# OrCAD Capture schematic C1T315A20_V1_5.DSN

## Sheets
1 000_LOG: title: TELINK; rev: V1.4; note: C1T315A20
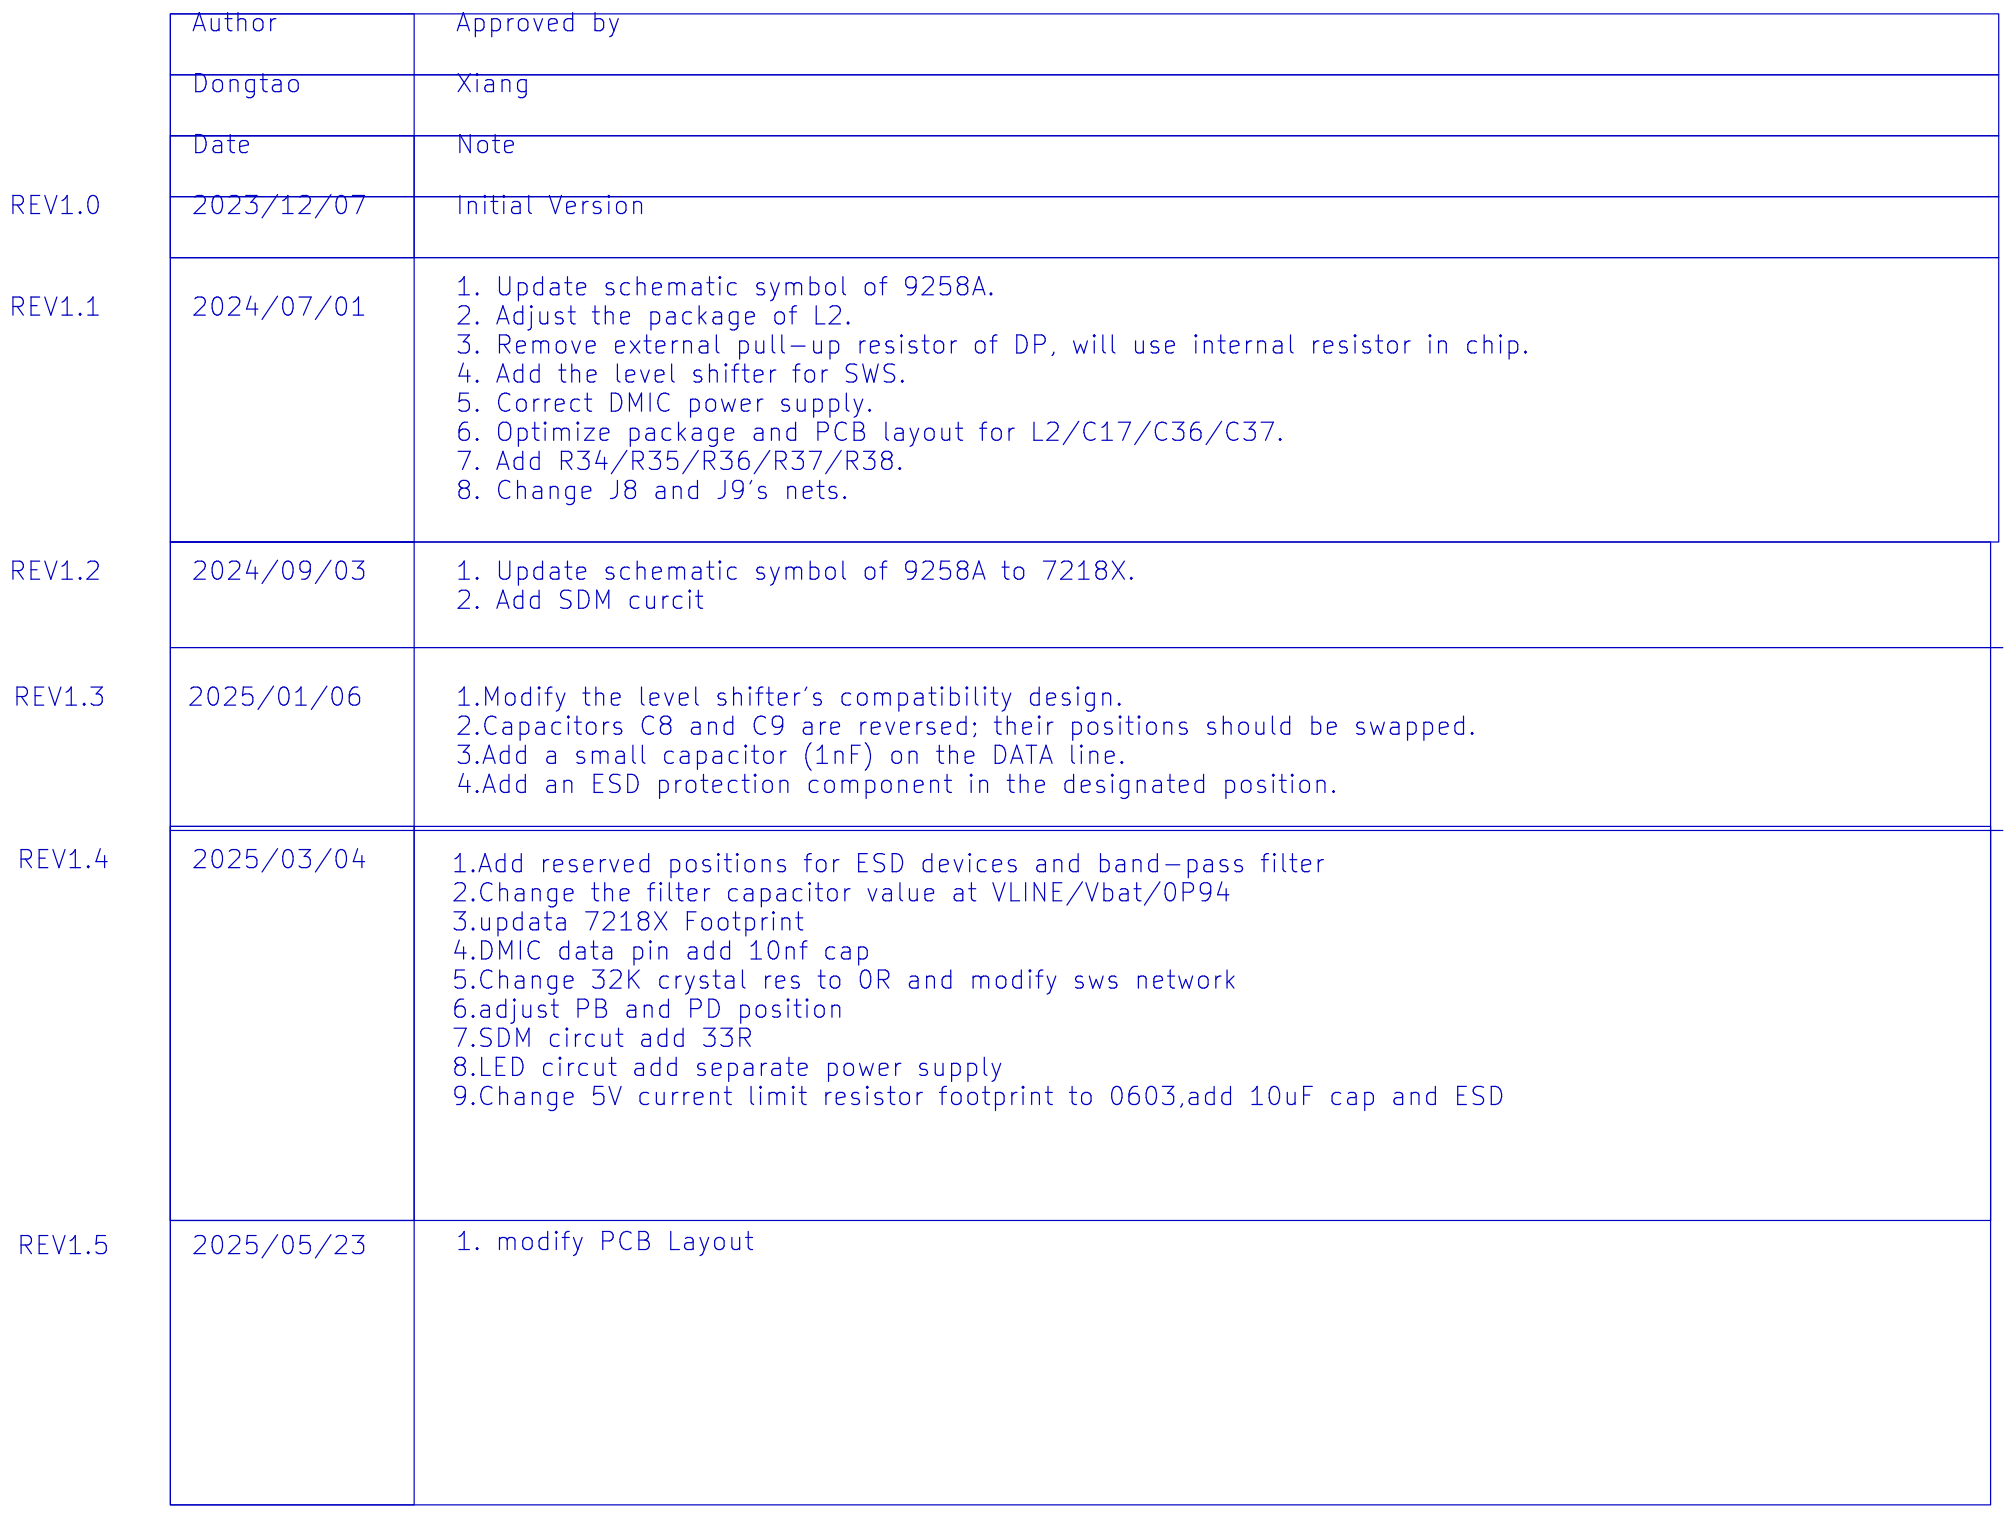
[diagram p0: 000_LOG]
2 001_STR: rev: V1.5
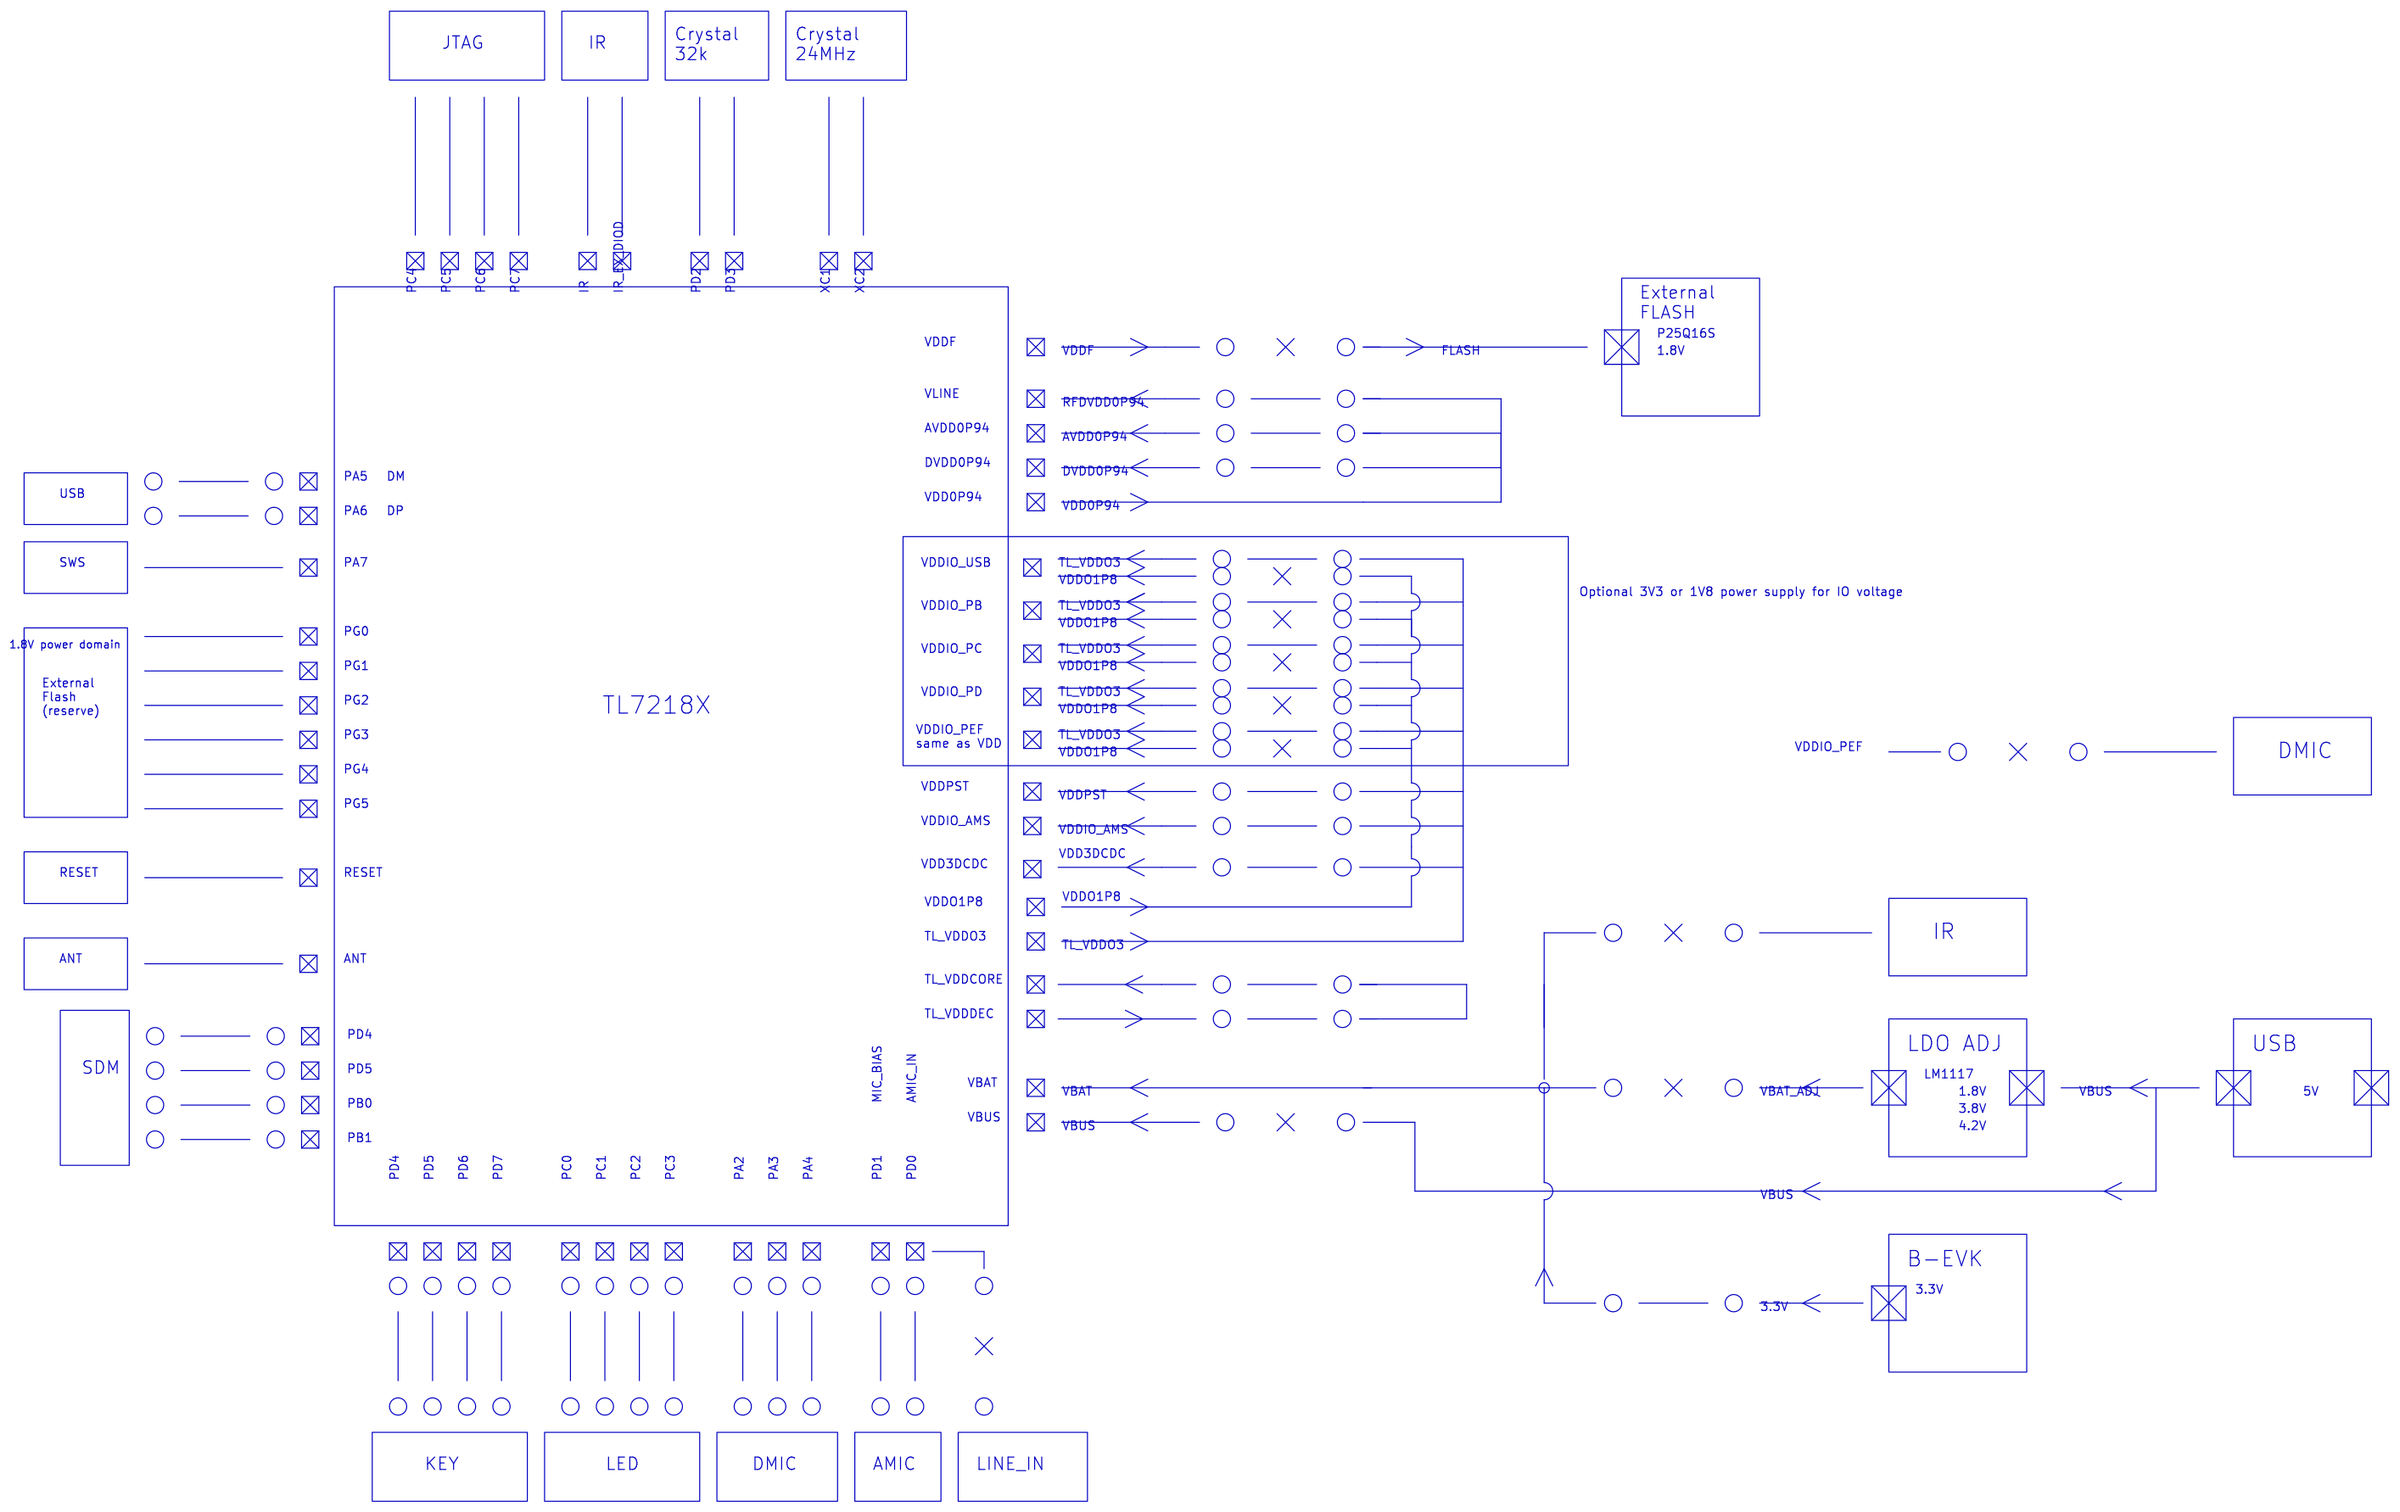
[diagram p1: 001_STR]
3 002_MAIN: size A3; rev: V1.5
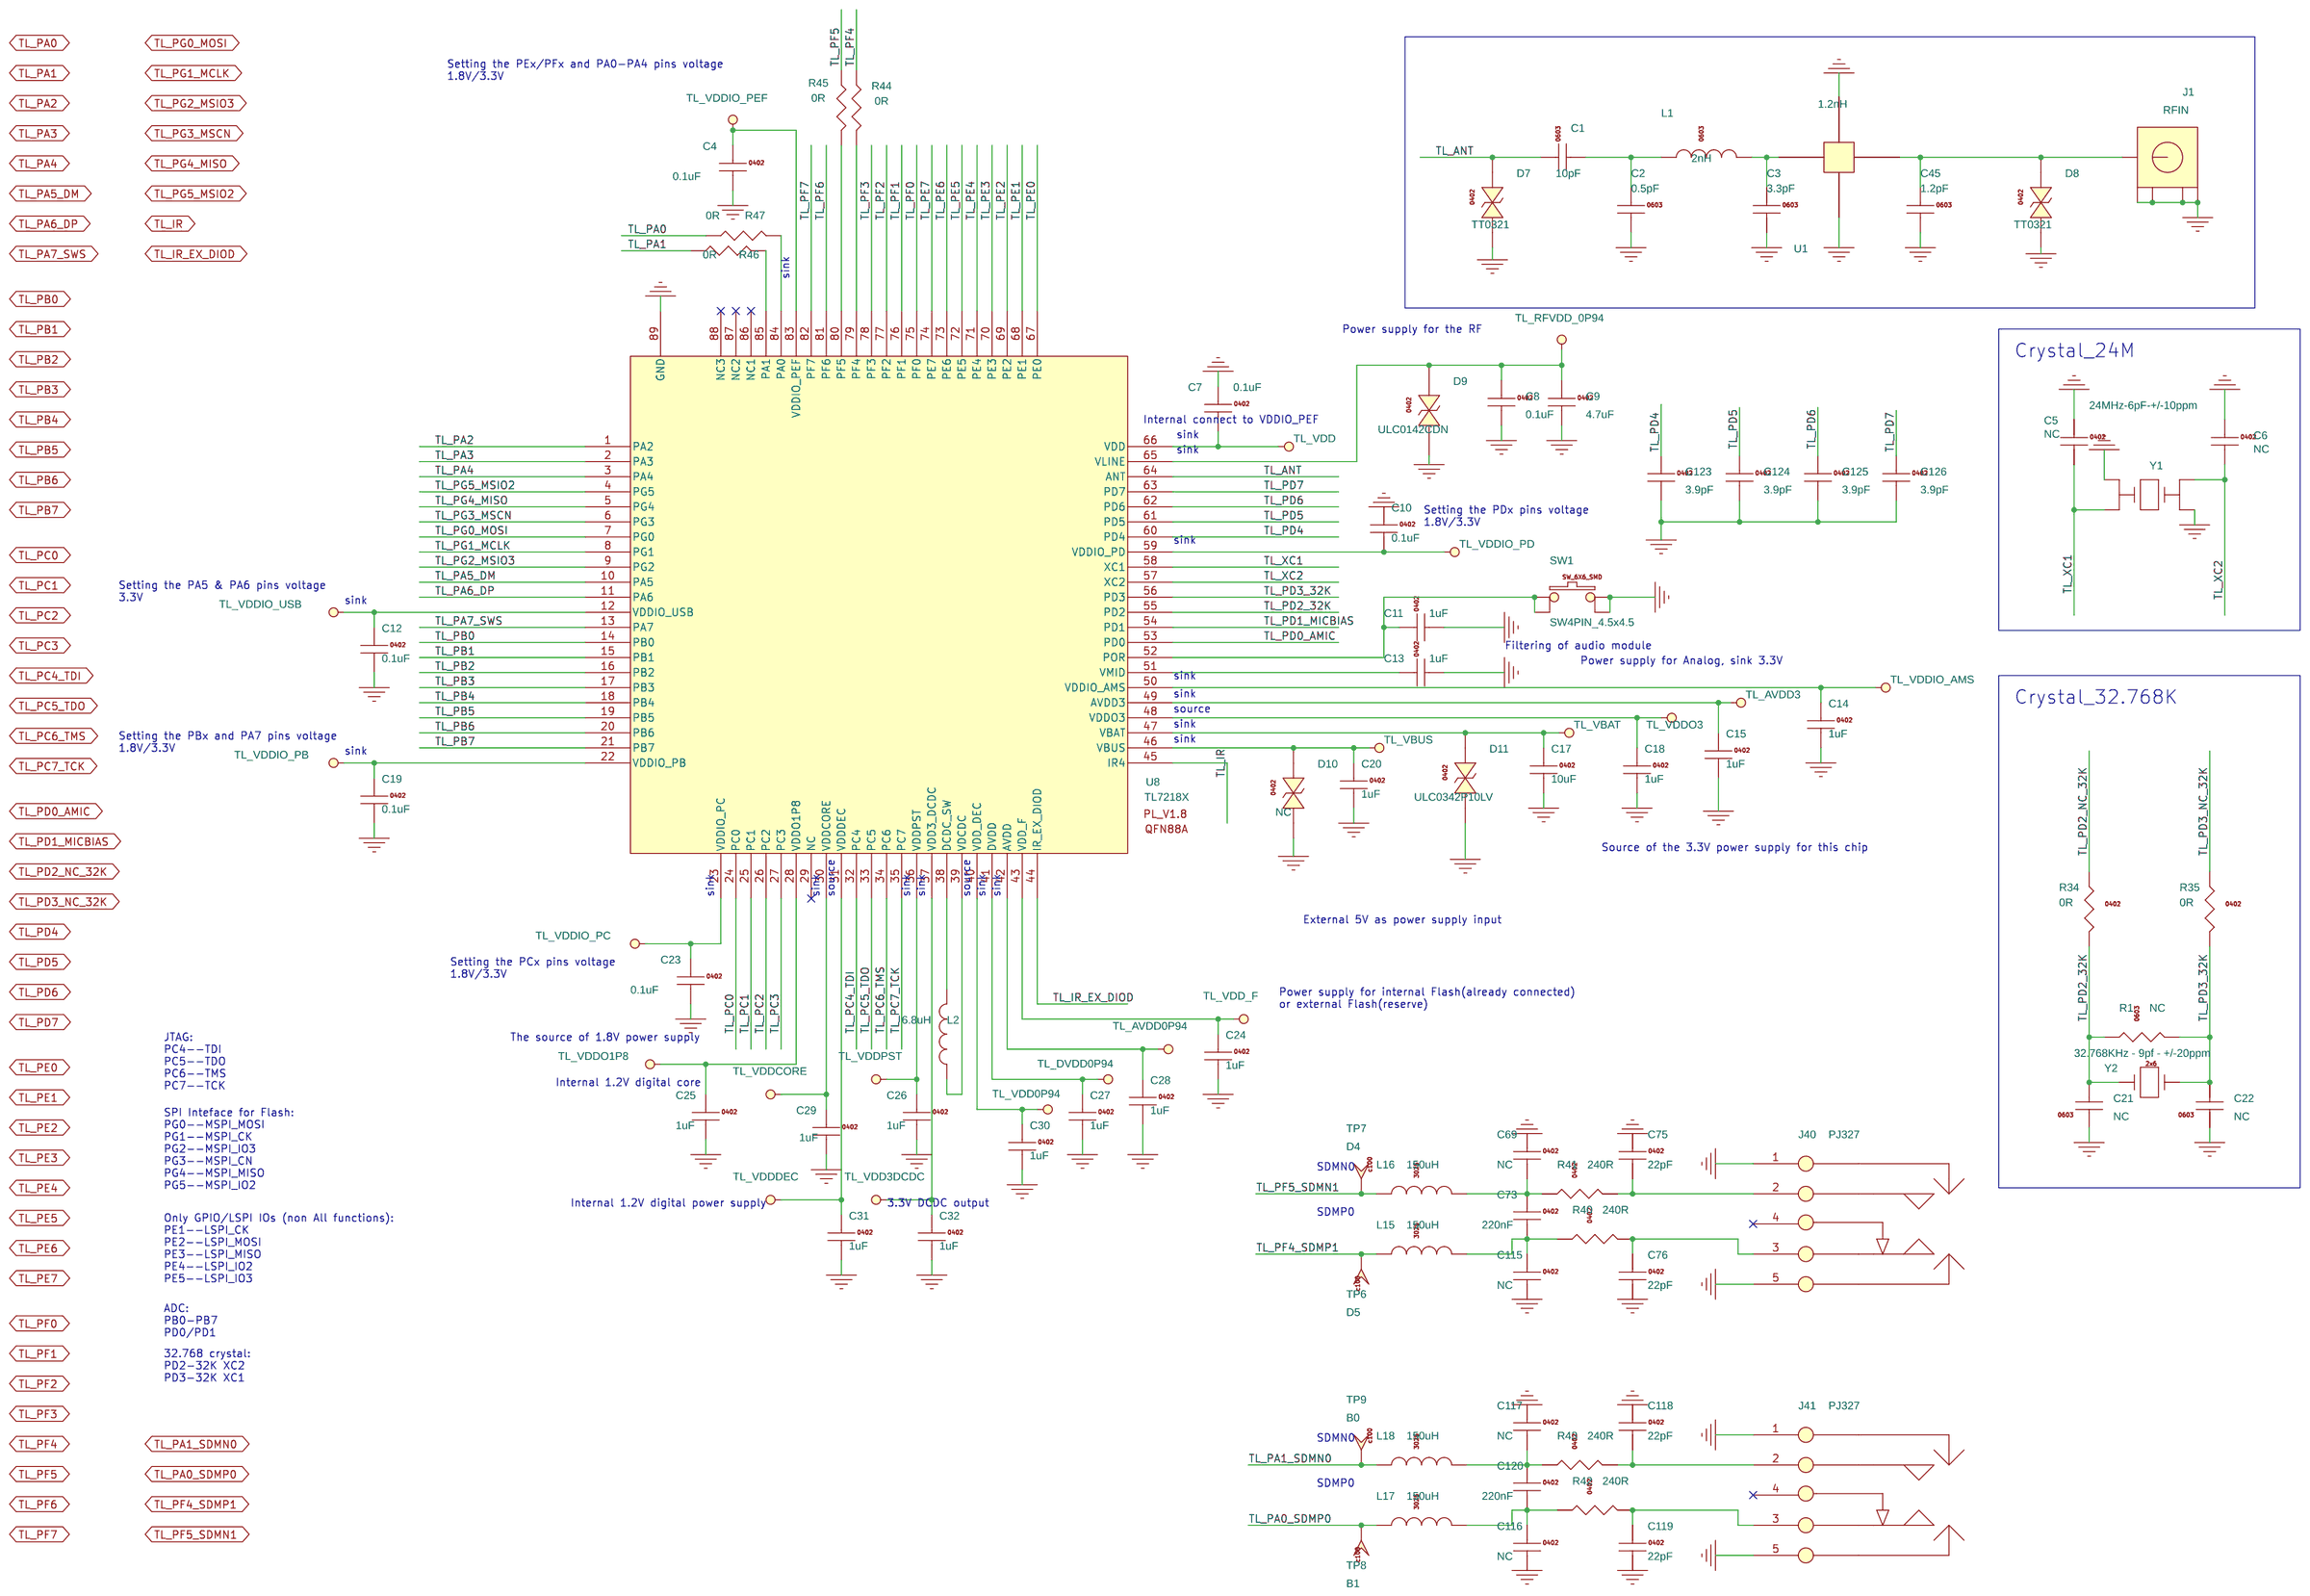
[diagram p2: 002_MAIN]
4 003_INTERFACE: size A3; rev: V1.5
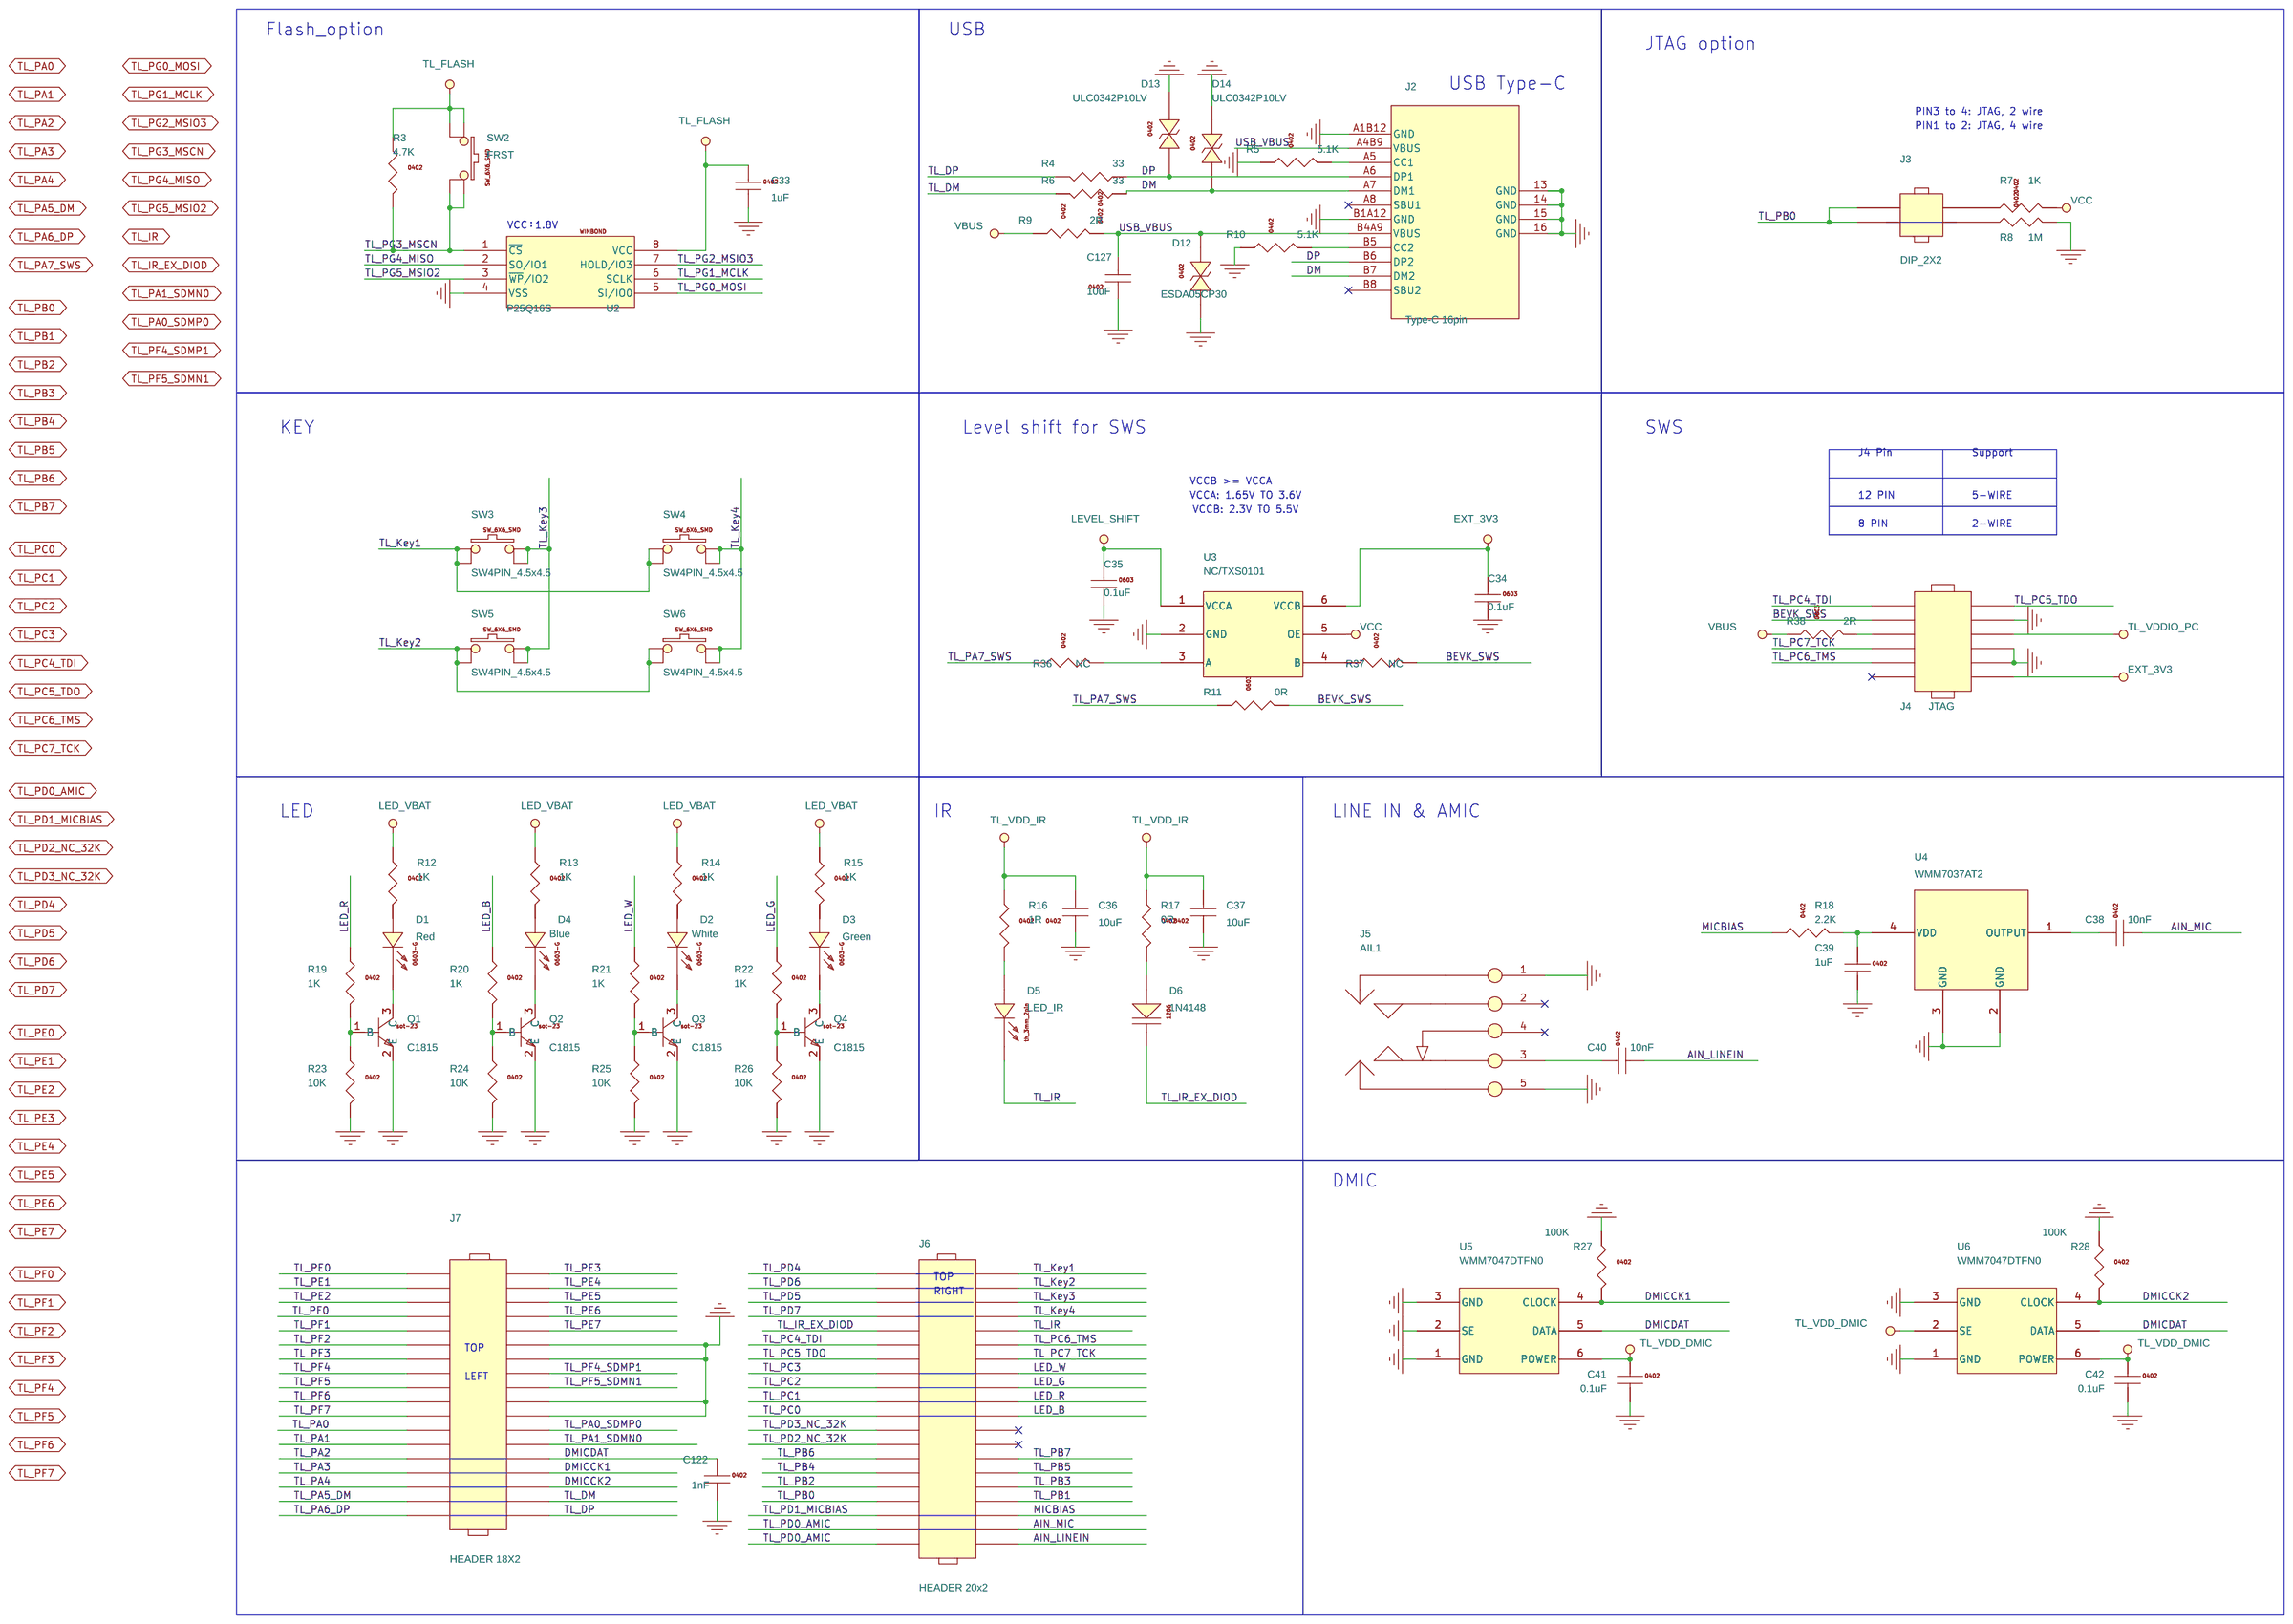
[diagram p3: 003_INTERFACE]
5 004_POWER: size A4; rev: V1.5
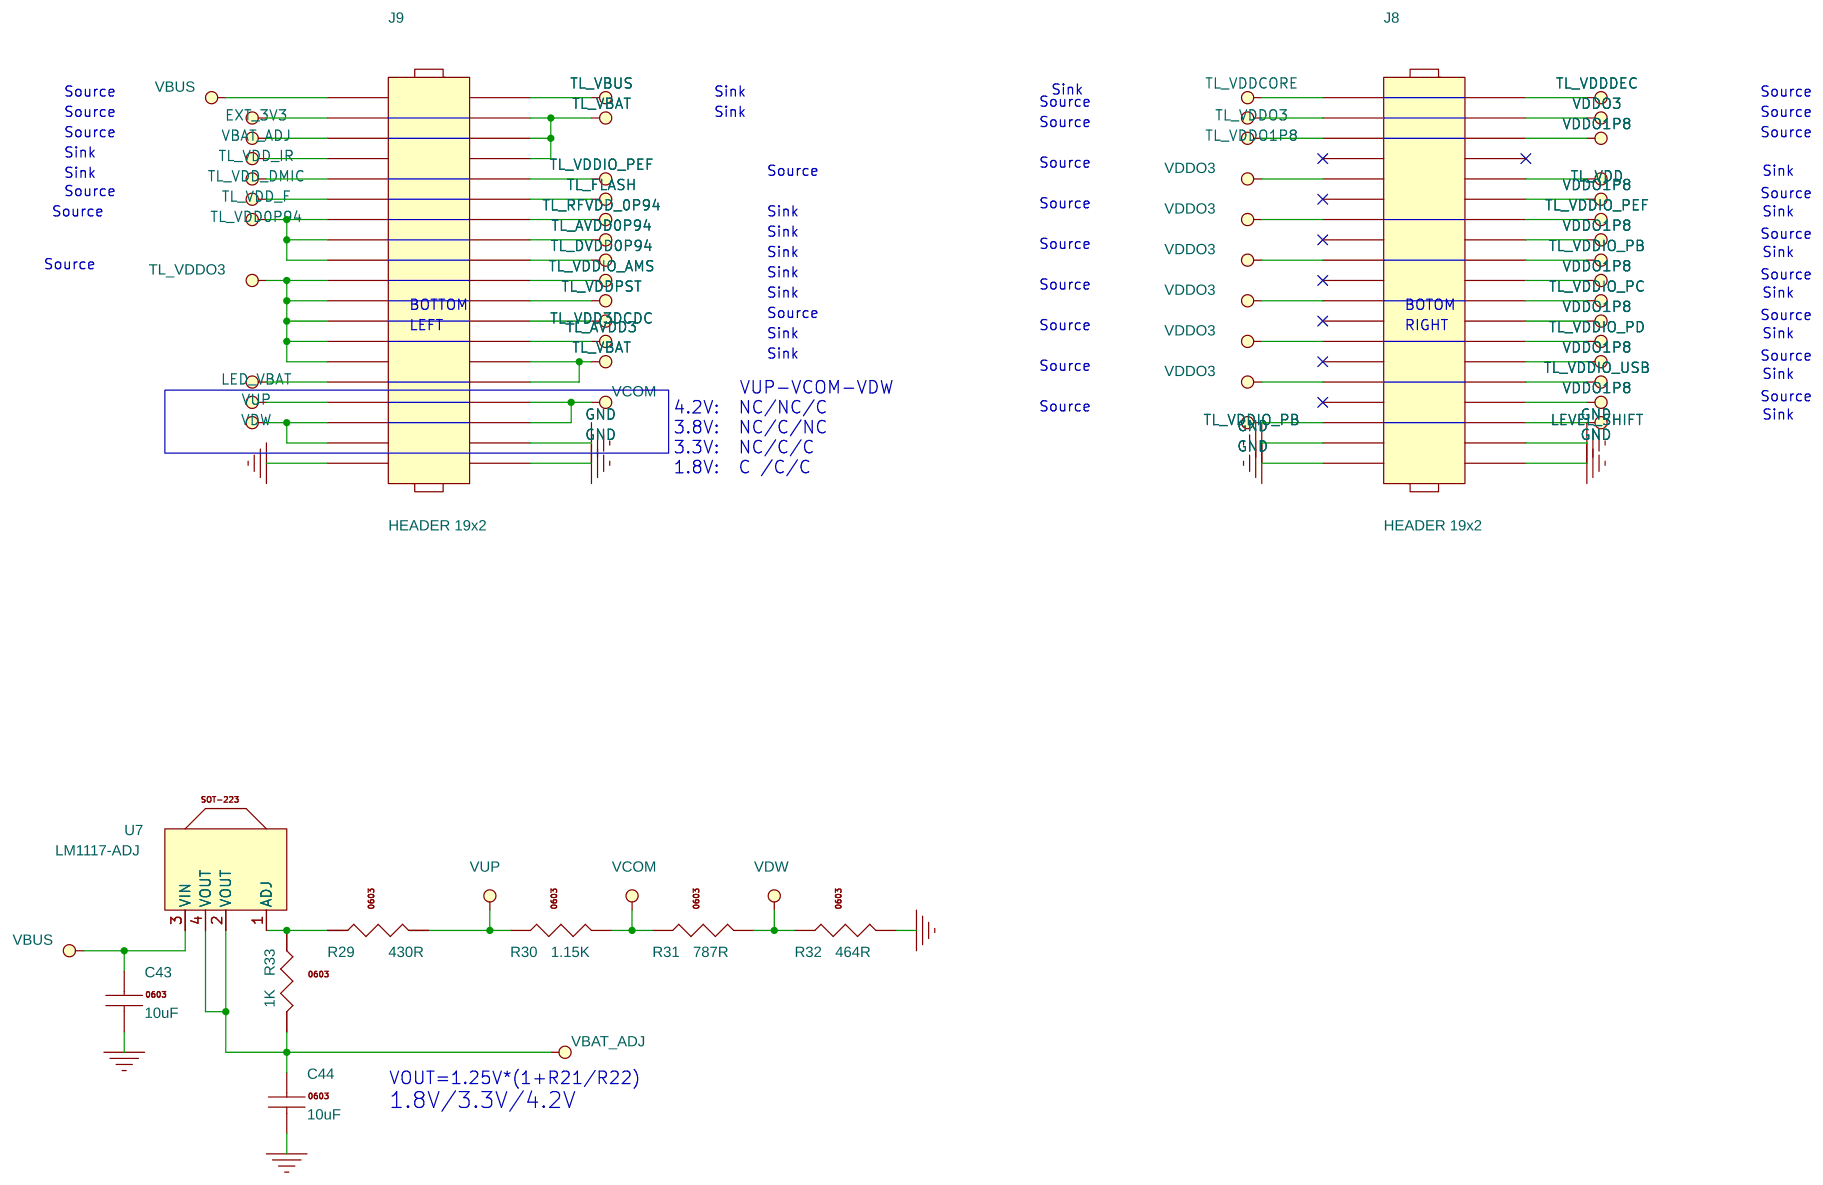
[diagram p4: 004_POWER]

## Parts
sheet 002_MAIN
C1  10pF  [0402]
C2  0.5pF  [0402]
C3  3.3pF  [0402]
C4  0.1uF  [0402]
C5  NC  [0402]
C6  NC  [0402]
C7  0.1uF  [0402]
C8  0.1uF  [0402]
C9  4.7uF  [0402]
C10  0.1uF  [0402]
C11  1uF  [0402]
C12  0.1uF  [0402]
C13  1uF  [0402]
C14  1uF  [0402]
C15  1uF  [0402]
C17  10uF  [0603C]
C18  1uF  [0402]
C19  0.1uF  [0402]
C20  1uF  [0402]
C21  NC  [0402]
C22  NC  [0402]
C23  0.1uF  [0402]
C24  1uF  [0402]
C25  1uF  [0402]
C26  1uF  [0402]
C27  1uF  [0402]
C28  1uF  [0402]
C29  1uF  [0402]
C30  1uF  [0402]
C31  1uF  [0402]
C32  1uF  [0402]
C45  1.2pF  [0402]
C69  NC  [0402]
C73  220nF  [0402]
C75  22pF  [0402]
C76  22pF  [0402]
C115  NC  [0402]
C116  NC  [0402]
C117  NC  [0402]
C118  22pF  [0402]
C119  22pF  [0402]
C120  220nF  [0402]
C123  3.9pF  [0402]
C124  3.9pF  [0402]
C125  3.9pF  [0402]
C126  3.9pF  [0402]
D7  TT0321  [0402]
D8  TT0321  [0402]
D9  ULC0142CDN  [0402]
D10  NC  [0402]
D11  ULC0342P10LV  [0402]
J1  RFIN  [SMA-H]
J40  PJ327  [PJ-327]
J41  PJ327  [PJ-327]
L1  2nH  [0402]
L2  6.8uH  [1008L]
L15  150uH  [INDM3025X25]
L16  150uH  [INDM3025X25]
L17  150uH  [INDM3025X25]
L18  150uH  [INDM3025X25]
R1  NC  [0402]
R34  0R  [0402]
R35  0R  [0402]
R40  240R  [0402R]
R41  240R  [0402R]
R42  240R  [0402R]
R43  240R  [0402R]
R44  0R  [0402r]
R45  0R  [0402r]
R46  0R  [0402r]
R47  0R  [0402r]
SW1  SW4PIN_4.5x4.5  [SW_6X6_SMD]
TP6  D5  [TP100]
TP7  D4  [TP100]
TP8  B1  [TP100]
TP9  B0  [TP100]
U1  1.2nH  [bandpass]
U8  TL7218X  [qfn_9x9_88pin_0p35_6p50x6p50]
Y1  24MHz-6pF-+/-10ppm  [OSCCC250X320X110]
Y2  32.768KHz - 9pf - +/-20ppm  [OSC_2x6]
sheet 003_INTERFACE
C33  1uF  [0402]
C34  0.1uF  [0402]
C35  0.1uF  [0402]
C36  10uF  [0603C]
C37  10uF  [0603C]
C38  10nF  [0402]
C39  1uF  [0402]
C40  10nF  [0402]
C41  0.1uF  [0402]
C42  0.1uF  [0402]
C122  1nF  [0402]
C127  10uF  [0402]
D1  Red  [0603-LED]
D2  White  [0603-LED]
D3  Green  [0603-LED]
D4  Blue  [0603-LED]
D5  LED_IR  [led_th_2p54mm_2pin]
D6  1N4148  [SOD80]
D12  ESDA05CP30  [0402]
D13  ULC0342P10LV  [0402]
D14  ULC0342P10LV  [0402]
J2  Type-C 16pin  [type_c_cq_105pwb]
J3  DIP_2X2  [DipSwitch_2p54_7p62_2x2]
J4  JTAG  [hdr254f-2x6x850]
J5  AIL1  [PJ-327]
J6  HEADER 20x2  [smd254m-2x20_rx1_30y2_40]
J7  HEADER 18X2  [smd254m-2x18_rx1_30y2_40]
Q1  C1815  [SOT-23]
Q2  C1815  [SOT-23]
Q3  C1815  [SOT-23]
Q4  C1815  [SOT-23]
R3  4.7K  [0402]
R4  33  [0402]
R5  5.1K  [0402]
R6  33  [0402]
R7  1K  [0402]
R8  1M  [0402]
R9  2R  [0603r]
R10  5.1K  [0402]
R11  0R  [0402]
R12  1K  [0402]
R13  1K  [0402]
R14  1K  [0402]
R15  1K  [0402]
R16  1R  [0402]
R17  0R  [0402]
R18  2.2K  [0402]
R19  1K  [0402]
R20  1K  [0402]
R21  1K  [0402]
R22  1K  [0402]
R23  10K  [0402]
R24  10K  [0402]
R25  10K  [0402]
R26  10K  [0402]
R27  100K  [0402]
R28  100K  [0402]
R36  NC  [0402]
R37  NC  [0402]
R38  2R  [0603r]
SW2  FRST  [SW_6X6_SMD]
SW3  SW4PIN_4.5x4.5  [SW_6X6_SMD]
SW4  SW4PIN_4.5x4.5  [SW_6X6_SMD]
SW5  SW4PIN_4.5x4.5  [SW_6X6_SMD]
SW6  SW4PIN_4.5x4.5  [SW_6X6_SMD]
U2  P25Q16S  [W25X10_20_40BL]
U3  NC/TXS0101  [sc70-6]
U4  WMM7037AT2  [ga_bfa423_a83]
U5  WMM7047DTFN0  [DMIC_SPM0423HM4H-WB]
U6  WMM7047DTFN0  [DMIC_SPM0423HM4H-WB]
sheet 004_POWER
C43  10uF  [0603c]
C44  10uF  [0603C]
J8  HEADER 19x2  [HDR2X19-2R54-SM-M]
J9  HEADER 19x2  [HDR2X19-2R54-SM-M]
R29  430R  [0402]
R30  1.15K  [0402]
R31  787R  [0402]
R32  464R  [0402]
R33  1K  [0402]
U7  LM1117-ADJ  [sot-223]

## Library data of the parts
C1-C3 C21 C22 C45 = C1608_NC
C4 C7-C15 C17-C20 C23-C33 C36-C40 C123-C127 = C1005X5R1C104K
C5 C6 C69 C115-C117 = C1005_NC
C73 C120 = C1005X5R1C224M
C75 C76 C118 C119 = C1005C0G1H100D
D7 D13 D14 = ESD5B5_2.0ST1G
D8-D12 = ESD5B5_3.0ST1G
J1 = SMA_JACK_2: PART: RF
J5 J40 J41 = PJ327_2
L1 = MLK1608_000R
L2 = IND_0
L15-L18 = IND_150uH_3025
R1 R11 = RS0603K102JT
R19-R26 R34 R35 = RS0402K101JT
R40-R43 = RS0402K330JT
R44 R46 R47 = R_7
R45 = R_6
SW1 SW3-SW6 = SW_6X6_SMD_0
TP6-TP9 = TestPad100
U1 = 4_HEADER_3
U8 = TL7218X-TLSR9258A-QFN88A
Y1 = CRYSTAL4_SM_0
Y2 = OSC_2x6_2pin_16Mhz
C34 C35 C44 = C1608X5R1C105M
C41 C42 C122 = C1005X5R1C104K_1
D1-D4 = 0603D_Green
D5 = Led_Th_3mm_1
D6 = Diode_1N4148
J2 = Type-C_16pin_0
J3 = HEADER_2X2_0
J4 = HEADER_6X2
J6 = HEADER_20x2_M
J7 = HEADER_18X2
Q1-Q4 = NPN_C1815
R3 R7 R8 R18 R27 R28 R36 R37 = RS0402K104JT
R4-R6 R9 R10 = RS0402K330JT: ROOM: USB
R12-R17 = RS0402K102JT
R29-R33 R38 = RS0603K104JT
SW2 = SW_6X6_SMD
U2 = GD25LD40C_0
U3 = TXS0101
U4 = MULPS4CX-RM5_0
U5 U6 = LD1117_SO_0
C43 = C1608X5R0J106M
J8 J9 = HEADER_19x2
U7 = XC62FP3302_0.3V_SOT-89

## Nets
GND: C2.2 C3.2 C4.2 C5.1 C6.1 C7.1 C8.2 C9.2 C10.1 C11.2 C12.2 C13.2 C14.2 C15.2 C17.2 C18.2 C19.2 C20.2 C21.1 C22.1 C23.2 C24.2 C25.2 C26.2 C27.2 C28.2 C29.2 C30.2 C31.2 C32.2 C33.2 C34.2 C35.2 C36.1 C37.1 C39.2 C41.2 C42.2 C43.2 C44.2 C45.2 C69.1 C75.1 C76.2 C115.2 C116.2 C117.1 C118.1 C119.2 C122.2 C123.2 C124.2 C125.2 C126.2 C127.1 D7.1 D8.1 D9.1 D10.1 D11.1 D12.1 D13.2 D14.2 J1.2 J1.3 J1.4 J1.5 J2.13(GND) J2.14(GND) J2.15(GND) J2.16(GND) J2.A1B12(GND) J2.B1A12(GND) J4.3 J4.5 J4.9 J5.1 J5.5 J7.11 J7.13 J7.19 J7.21 J8.35 J8.36 J8.37 J8.38 J9.35 J9.37 J9.38 J40.1 J40.5 J41.1 J41.5 Q1.2(E) Q2.2(E) Q3.2(E) Q4.2(E) R5.1 R8.2 R10.1 R23.2 R24.2 R25.2 R26.2 R27.1 R28.1 R32.2 SW1.3 SW1.4 U1.1 U1.3 U2.4(VSS) U3.2(GND) U4.2(GND) U4.3(GND) U5.1(GND) U5.2(SE) U5.3(GND) U6.1(GND) U6.3(GND) U8.89(GND) Y1.2 Y1.4
VBAT_ADJ: C44.1 J9.6 R33.2 U7.2(VOUT) U7.4(VOUT)
VBUS: C43.1 J9.2 R9.1 R38.1 U7.3(VIN)
VDDO1P8: J8.5 J8.11 J8.15 J8.19 J8.23 J8.27 J8.31
VDDO3: J8.3 J8.10 J8.14 J8.18 J8.22 J8.26 J8.30
AIN_LINEIN: C40.2 J6.39
AIN_MIC: C38.2 J6.37
BEVK_SWS: J4.10 R11.2 R37.2
DM: D14.1 J2.A7(DM1) J2.B7(DM2) R6.1
DMICCK1: J7.29 R27.2 U5.4(CLOCK)
DMICCK2: J7.31 R28.2 U6.4(CLOCK)
DMICDAT: C122.1 J7.27 U5.5(DATA) U6.5(DATA)
DP: D13.1 J2.A6(DP1) J2.B6(DP2) R4.1
EXT_3V3: C34.1 J4.1 J9.4 U3.6(VCCB)
LED_B: J6.21 R20.1
LED_G: J6.17 R22.1
LED_R: J6.19 R19.1
LED_VBAT: J9.30 R12.1 R13.1 R14.1 R15.1
LED_W: J6.15 R21.1
LEVEL_SHIFT: C35.1 J8.33 U3.1(VCCA) U3.5(OE)
MICBIAS: J6.35 R18.1
TL_ANT: C1.1 D7.2 U8.64(ANT)
TL_AVDD0P94: C28.1 J9.15 U8.42(AVDD)
TL_AVDD3: C15.1 J9.25 U8.49(AVDD3)
TL_DM: J7.33 R6.2
TL_DP: J7.35 R4.2
TL_DVDD0P94: C27.1 J9.17 U8.41(DVDD)
TL_FLASH: C33.1 J9.11 R3.1 SW2.1 SW2.2 U2.8(VCC)
TL_IR: U8.45(IR4)
TL_IR (page 003_INTERFACE): D5.C(CATHODE) J6.9
TL_IR_EX_DIOD: U8.44(IR_EX_DIOD)
TL_IR_EX_DIOD (page 003_INTERFACE): D6.C J6.10
TL_Key1: J6.1 SW3.1 SW3.2 SW4.1 SW4.2
TL_Key2: J6.3 SW5.1 SW5.2 SW6.1 SW6.2
TL_Key3: J6.5 SW3.3 SW3.4 SW5.3 SW5.4
TL_Key4: J6.7 SW4.3 SW4.4 SW6.3 SW6.4
TL_PA0: R47.1
TL_PA0 (page 003_INTERFACE): J7.24
TL_PA0_SDMP0: L17.1 TP8.1(TP)
TL_PA0_SDMP0 (page 003_INTERFACE): J7.23
TL_PA1: R46.1
TL_PA1 (page 003_INTERFACE): J7.26
TL_PA1_SDMN0: L18.1 TP9.1(TP)
TL_PA1_SDMN0 (page 003_INTERFACE): J7.25
TL_PA2: U8.1(PA2)
TL_PA2 (page 003_INTERFACE): J7.28
TL_PA3: U8.2(PA3)
TL_PA3 (page 003_INTERFACE): J7.30
TL_PA4: U8.3(PA4)
TL_PA4 (page 003_INTERFACE): J7.32
TL_PA5_DM: U8.10(PA5)
TL_PA5_DM (page 003_INTERFACE): J7.34
TL_PA6_DP: U8.11(PA6)
TL_PA6_DP (page 003_INTERFACE): J7.36
TL_PA7_SWS: U8.13(PA7)
TL_PA7_SWS (page 003_INTERFACE): R11.1 R36.1
TL_PB0: U8.14(PB0)
TL_PB0 (page 003_INTERFACE): J3.1 J3.3 J6.34
TL_PB1: U8.15(PB1)
TL_PB1 (page 003_INTERFACE): J6.33
TL_PB2: U8.16(PB2)
TL_PB2 (page 003_INTERFACE): J6.32
TL_PB3: U8.17(PB3)
TL_PB3 (page 003_INTERFACE): J6.31
TL_PB4: U8.18(PB4)
TL_PB4 (page 003_INTERFACE): J6.30
TL_PB5: U8.19(PB5)
TL_PB5 (page 003_INTERFACE): J6.29
TL_PB6: U8.20(PB6)
TL_PB6 (page 003_INTERFACE): J6.28
TL_PB7: U8.21(PB7)
TL_PB7 (page 003_INTERFACE): J6.27
TL_PC0: U8.24(PC0)
TL_PC0 (page 003_INTERFACE): J6.22
TL_PC1: U8.25(PC1)
TL_PC1 (page 003_INTERFACE): J6.20
TL_PC2: U8.26(PC2)
TL_PC2 (page 003_INTERFACE): J6.18
TL_PC3: U8.27(PC3)
TL_PC3 (page 003_INTERFACE): J6.16
TL_PC4_TDI: U8.32(PC4)
TL_PC4_TDI (page 003_INTERFACE): J4.12 J6.12
TL_PC5_TDO: U8.33(PC5)
TL_PC5_TDO (page 003_INTERFACE): J4.11 J6.14
TL_PC6_TMS: U8.34(PC6)
TL_PC6_TMS (page 003_INTERFACE): J4.4 J6.11
TL_PC7_TCK: U8.35(PC7)
TL_PC7_TCK (page 003_INTERFACE): J4.6 J6.13
TL_PD0_AMIC: U8.53(PD0)
TL_PD0_AMIC (page 003_INTERFACE): J6.38 J6.40
TL_PD1_MICBIAS: U8.54(PD1)
TL_PD1_MICBIAS (page 003_INTERFACE): J6.36
TL_PD2_32K: C21.2 R1.1 R34.2 U8.55(PD2) Y2.1
TL_PD2_NC_32K: R34.1
TL_PD2_NC_32K (page 003_INTERFACE): J6.26
TL_PD3_32K: C22.2 R1.2 R35.2 U8.56(PD3) Y2.2
TL_PD3_NC_32K: R35.1
TL_PD3_NC_32K (page 003_INTERFACE): J6.24
TL_PD4: C123.1 U8.60(PD4)
TL_PD4 (page 003_INTERFACE): J6.2
TL_PD5: C124.1 U8.61(PD5)
TL_PD5 (page 003_INTERFACE): J6.6
TL_PD6: C125.1 U8.62(PD6)
TL_PD6 (page 003_INTERFACE): J6.4
TL_PD7: C126.1 U8.63(PD7)
TL_PD7 (page 003_INTERFACE): J6.8
TL_PE0: U8.67(PE0)
TL_PE0 (page 003_INTERFACE): J7.2
TL_PE1: U8.68(PE1)
TL_PE1 (page 003_INTERFACE): J7.4
TL_PE2: U8.69(PE2)
TL_PE2 (page 003_INTERFACE): J7.6
TL_PE3: U8.70(PE3)
TL_PE3 (page 003_INTERFACE): J7.1
TL_PE4: U8.71(PE4)
TL_PE4 (page 003_INTERFACE): J7.3
TL_PE5: U8.72(PE5)
TL_PE5 (page 003_INTERFACE): J7.5
TL_PE6: U8.73(PE6)
TL_PE6 (page 003_INTERFACE): J7.7
TL_PE7: U8.74(PE7)
TL_PE7 (page 003_INTERFACE): J7.9
TL_PF0: U8.75(PF0)
TL_PF0 (page 003_INTERFACE): J7.8
TL_PF1: U8.76(PF1)
TL_PF1 (page 003_INTERFACE): J7.10
TL_PF2: U8.77(PF2)
TL_PF2 (page 003_INTERFACE): J7.12
TL_PF3: U8.78(PF3)
TL_PF3 (page 003_INTERFACE): J7.14
TL_PF4: R44.1
TL_PF4 (page 003_INTERFACE): J7.16
TL_PF4_SDMP1: L15.1 TP6.1(TP)
TL_PF4_SDMP1 (page 003_INTERFACE): J7.15
TL_PF5: R45.1
TL_PF5 (page 003_INTERFACE): J7.18
TL_PF5_SDMN1: L16.1 TP7.1(TP)
TL_PF5_SDMN1 (page 003_INTERFACE): J7.17
TL_PF6: U8.81(PF6)
TL_PF6 (page 003_INTERFACE): J7.20
TL_PF7: U8.82(PF7)
TL_PF7 (page 003_INTERFACE): J7.22
TL_PG0_MOSI: U8.7(PG0)
TL_PG0_MOSI (page 003_INTERFACE): U2.5(SI/IO0)
TL_PG1_MCLK: U8.8(PG1)
TL_PG1_MCLK (page 003_INTERFACE): U2.6(SCLK)
TL_PG2_MSIO3: U8.9(PG2)
TL_PG2_MSIO3 (page 003_INTERFACE): U2.7(HOLD/IO3)
TL_PG3_MSCN: U8.6(PG3)
TL_PG3_MSCN (page 003_INTERFACE): R3.2 SW2.3 SW2.4 U2.1(~{CS})
TL_PG4_MISO: U8.5(PG4)
TL_PG4_MISO (page 003_INTERFACE): U2.2(SO/IO1)
TL_PG5_MSIO2: U8.4(PG5)
TL_PG5_MSIO2 (page 003_INTERFACE): U2.3(~{WP}/IO2)
TL_RFVDD_0P94: C8.1 C9.1 D9.2 J9.13 U8.65(VLINE)
TL_VBAT: C17.1 D11.2 J9.3 J9.5 J9.7 J9.27 J9.29 U8.47(VBAT)
TL_VBUS: C20.1 D10.2 J9.1 U8.46(VBUS)
TL_VDD: C7.2 J8.9 U8.66(VDD)
TL_VDD0P94: C30.1 J9.14 J9.16 J9.18 U8.40(VDD_DEC)
TL_VDD3DCDC: C32.1 J9.23 U8.37(VDD3_DCDC)
TL_VDD_DMIC: C41.1 C42.1 J9.10 U5.6(POWER) U6.2(SE) U6.6(POWER)
TL_VDD_F: C24.1 J9.12 U8.43(VDD_F)
TL_VDD_IR: C36.2 C37.2 J9.8 R16.1 R17.1
TL_VDDCORE: C29.1 J8.2 U8.30(VDDCORE)
TL_VDDDEC: C31.1 J8.1 U8.31(VDDDEC)
TL_VDDIO_AMS: C14.1 J9.19 U8.50(VDDIO_AMS)
TL_VDDIO_PB: C19.1 J8.17 J8.34 U8.22(VDDIO_PB)
TL_VDDIO_PC: C23.1 J4.7 J8.21 U8.23(VDDIO_PC)
TL_VDDIO_PD: C10.2 J8.25 U8.59(VDDIO_PD)
TL_VDDIO_PEF: C4.1 J8.13 J9.9 U8.83(VDDIO_PEF)
TL_VDDIO_USB: C12.1 J8.29 U8.12(VDDIO_USB)
TL_VDDO1P8: C25.1 J8.6 U8.28(VDDO1P8)
TL_VDDO3: C18.1 J8.4 J9.20 J9.22 J9.24 J9.26 J9.28 R7.2 U8.48(VDDO3)
TL_VDDPST: C26.1 J9.21 U8.36(VDDPST)
TL_XC1: C5.2 U8.58(XC1) Y1.3
TL_XC2: C6.2 U8.57(XC2) Y1.1
USB_VBUS: C127.2 D12.2 J2.A4B9(VBUS) J2.B4A9(VBUS) R9.2
VCOM: J9.31 J9.33 R30.2 R31.1
VDW: J9.34 J9.36 R31.2 R32.1
VUP: J9.32 R29.2 R30.1
N20028206: R29.1 R33.1 U7.1(ADJ)
N20230476: Q1.1(B) R19.2 R23.1
N20230490: Q2.1(B) R20.2 R24.1
N20230526: Q3.1(B) R21.2 R25.1
N20230570: Q4.1(B) R22.2 R26.1
N20230742: D1.A(ANODE) R12.2
N20230744: D1.C(CATHODE) Q1.3(C)
N20230746: D4.A(ANODE) R13.2
N20230748: D4.C(CATHODE) Q2.3(C)
N20230750: D2.A(ANODE) R14.2
N20230752: D2.C(CATHODE) Q3.3(C)
N20230754: D3.A(ANODE) R15.2
N20230756: D3.C(CATHODE) Q4.3(C)
N20248227: C39.1 R18.2 U4.4(VDD)
N20254983: C38.1 U4.1(OUTPUT)
N20255175: C40.1 J5.3
N20271178: D5.A(ANODE) R16.2
N20271193: D6.A R17.2
N20286198: R45.2 U8.80(PF5)
N20286201: R44.2 U8.79(PF4)
N20286912: C11.1 SW1.1 SW1.2 U8.52(POR)
N20286959: C13.1 U8.51(VMID)
N20290975: L2.2 U8.38(DCDC_SW)
N20290977: L2.1 U8.39(VDCDC)
N20305837: J2.A5(CC1) R5.2
N20305839: J2.B5(CC2) R10.2
N20310970: C1.2 C2.1 L1.1
N20310976: C3.1 L1.2 U1.4
N20348750: J4.8 R38.2
N20353968: C69.2 C73.1 L16.2 R41.1
N20353978: C75.2 J40.2 R41.2
N20354017: C73.2 C115.1 L15.2 R40.1
N20354025: C76.1 J40.3 R40.2
N20354127: C117.2 C120.1 L18.2 R43.1
N20354137: C118.2 J41.2 R43.2
N20354176: C116.1 C120.2 L17.2 R42.1
N20354184: C119.1 J41.3 R42.2
N20364573: C45.1 D8.2 J1.1 U1.2
N20368232: R36.2 U3.3(A)
N20378065: R47.2 U8.84(PA0)
N20378070: R46.2 U8.85(PA1)
N20387426: R37.1 U3.4(B)
N20387430: J3.2 R8.1
N20387440: J3.4 R7.1

Not connected (* = marked no-connect by the designer): J2 A8(SBU1)* B8(SBU2)*; J4 2*; J5 2* 4*; J6 23* 25*; J8 7* 8* 12* 16* 20* 24* 28* 32*; J40 4*; J41 4*; U8 29(NC)* 86(NC1)* 87(NC2)* 88(NC3)*

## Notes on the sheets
sheet 1
- Author
- Approved by
- Dongtao
- Xiang
- Date
- Note
- REV1.0
- 2023/12/07
- Initial Version
- 1. Update schematic symbol of 9258A.
  2. Adjust the package of L2.
  3. Remove external pull-up resistor of DP, will use internal resistor in chip.
  4. Add the level shifter for SWS.
  5. Correct DMIC power supply.
  6. Optimize package and PCB layout for L2/C17/C36/C37.
  7. Add R34/R35/R36/R37/R38.
  8. Change J8 and J9's nets.
- REV1.1
- 2024/07/01
- REV1.2
- 2024/09/03
- 1. Update schematic symbol of 9258A to 7218X.
  2. Add SDM curcit
- REV1.3
- 2025/01/06
- 1.Modify the level shifter's compatibility design.
  2.Capacitors C8 and C9 are reversed; their positions should be swapped.
  3.Add a small capacitor (1nF) on the DATA line.
  4.Add an ESD protection component in the designated position.
- REV1.4
- 2025/03/04
- 1.Add reserved positions for ESD devices and band-pass filter
  2.Change the filter capacitor value at VLINE/Vbat/0P94
  3.updata 7218X Footprint
  4.DMIC data pin add 10nf cap
  5.Change 32K crystal res to 0R and modify sws network
  6.adjust PB and PD position
  7.SDM circut add 33R
  8.LED circut add separate power supply
  9.Change 5V current limit resistor footprint to 0603,add 10uF cap and ESD
- REV1.5
- 2025/05/23
- 1. modify PCB Layout
sheet 2
- Crystal
  32k
- Crystal
  24MHz
- JTAG
- IR
- PC4
- PC5
- PC6
- PC7
- IR
- IR_EX_DIOD
- PD2
- PD3
- XC1
- XC2
- External
  FLASH
- P25Q16S
- VDDF
- VDDF
- FLASH
- 1.8V
- VLINE
- RFDVDD0P94
- AVDD0P94
- AVDD0P94
- DVDD0P94
- PA5
- DM
- DVDD0P94
- USB
- VDD0P94
- PA6
- DP
- VDD0P94
- SWS
- PA7
- VDDIO_USB
- TL_VDDO3
- VDDO1P8
- VDDIO_PB
- TL_VDDO3
- Optional 3V3 or 1V8 power supply for IO voltage
- VDDO1P8
- 1.8V power domain
- PG0
- PG1
- VDDIO_PC
- TL_VDDO3
- VDDO1P8
- External
  Flash
  (reserve)
- PG2
- TL7218X
- VDDIO_PD
- TL_VDDO3
- VDDO1P8
- PG3
- VDDIO_PEF
  same as VDD
- TL_VDDO3
- VDDIO_PEF
- DMIC
- VDDO1P8
- PG4
- VDDPST
- PG5
- VDDPST
- VDDIO_AMS
- VDDIO_AMS
- VDD3DCDC
- VDD3DCDC
- RESET
- RESET
- VDDO1P8
- VDDO1P8
- IR
- TL_VDDO3
- TL_VDDO3
- ANT
- ANT
- TL_VDDCORE
- TL_VDDDEC
- PD4
- LDO ADJ
- USB
- SDM
- PD5
- VBAT
- VBAT
- VBAT_ADJ
- LM1117
- 1.8V
- VBUS
- 5V
- PB0
- MIC_BIAS
- AMIC_IN
- 3.8V
- VBUS
- VBUS
- 4.2V
- PB1
- PD4
- PD5
- PD6
- PD7
- PC0
- PC1
- PC2
- PC3
- PA2
- PA3
- PA4
- PD1
- PD0
- VBUS
- B-EVK
- 3.3V
- 3.3V
- KEY
- LED
- DMIC
- AMIC
- LINE_IN
sheet 3
- Setting the PEx/PFx and PA0-PA4 pins voltage
  1.8V/3.3V
- sink
- Power supply for the RF
- Crystal_24M
- Internal connect to VDDIO_PEF
- sink
- sink
- Setting the PDx pins voltage
  1.8V/3.3V
- sink
- Setting the PA5 & PA6 pins voltage
  3.3V
- sink
- Filtering of audio module
- Power supply for Analog, sink 3.3V
- sink
- sink
- Crystal_32.768K
- source
- Setting the PBx and PA7 pins voltage
  1.8V/3.3V
- sink
- sink
- sink
- Source of the 3.3V power supply for this chip
- sink
- sink
- source
- sink
- sink
- source
- sink
- sink
- External 5V as power supply input
- Setting the PCx pins voltage
  1.8V/3.3V
- Power supply for internal Flash(already connected)
  or external Flash(reserve)
- JTAG:
  PC4--TDI
  PC5--TDO
  PC6--TMS
  PC7--TCK
- The source of 1.8V power supply
- Internal 1.2V digital core
- SPI Inteface for Flash:
  PG0--MSPI_MOSI
  PG1--MSPI_CK
  PG2--MSPI_IO3
  PG3--MSPI_CN
  PG4--MSPI_MISO
  PG5--MSPI_IO2
- SDMN0
- Only GPIO/LSPI IOs (non All functions):
  PE1--LSPI_CK
  PE2--LSPI_MOSI
  PE3--LSPI_MISO
  PE4--LSPI_IO2
  PE5--LSPI_IO3
- Internal 1.2V digital power supply
- 3.3V DCDC output
- SDMP0
- ADC:
  PB0-PB7
  PD0/PD1
- 32.768 crystal:
  PD2-32K XC2
  PD3-32K XC1
- SDMN0
- SDMP0
sheet 4
- Flash_option
- USB
- JTAG option
- USB Type-C
- PIN3 to 4: JTAG, 2 wire
- PIN1 to 2: JTAG, 4 wire
- VCC：1.8V
- KEY
- Level shift for SWS
- SWS
- J4 Pin
- Support
- VCCB >= VCCA
- VCCA: 1.65V TO 3.6V
- 12 PIN
- 5-WIRE
- VCCB: 2.3V TO 5.5V
- 8 PIN
- 2-WIRE
- LED
- IR
- LINE IN & AMIC
- DMIC
- TOP
- RIGHT
- TOP
- LEFT
sheet 5
- Source
- Sink
- Source
- Sink
- Source
- Source
- Source
- Sink
- Source
- Source
- Source
- Sink
- Sink
- Source
- Source
- Sink
- Source
- Source
- Source
- Source
- Sink
- Sink
- Sink
- Sink
- Source
- Source
- Sink
- Source
- Sink
- Source
- Sink
- Source
- Sink
- BOTTOM
- LEFT
- Source
- Source
- BOTOM
- RIGHT
- Source
- Sink
- Sink
- Sink
- Source
- Source
- VUP-VCOM-VDW
  4.2V:  NC/NC/C
  3.8V:  NC/C/NC
  3.3V:  NC/C/C
  1.8V:  C /C/C
- Source
- Sink
- Source
- Sink
- VOUT=1.25V*(1+R21/R22)
- 1.8V/3.3V/4.2V
